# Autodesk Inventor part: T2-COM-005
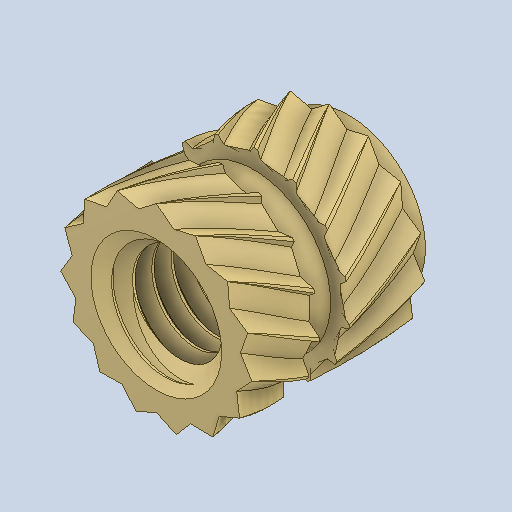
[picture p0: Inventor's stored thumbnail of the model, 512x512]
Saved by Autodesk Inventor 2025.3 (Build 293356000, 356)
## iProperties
Created: 2022-05
Part Number: T2-COM-005
Material: Genérico
Document SubType Name: Modeling
Designer: Luis MuÃ±oz
Density: 1 g/cm^3
Appearance: Valor por defecto
Project: TESIS 2 - Plataforma mecatrÃ³nica preventiva desacoplada
Description: Inserto roscado M3, Ø5 × 5 mm
Preprocessor: ST-DEVELOPER v16.5
Title: Inserto roscado M3, Ã˜5 Ã— 5 mm
Revision Number: 00
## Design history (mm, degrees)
feature "brep_1"
sketch "Boceto1"
  geometry: C1 r 4.084 at (-0.38, 0); 1 further point
  constraints: 1 centre point
extrude "Extrusión1" cut sketch "Boceto1" distance "d0" = 1; taper "d1" = 0 deg
node "Sólido1"
